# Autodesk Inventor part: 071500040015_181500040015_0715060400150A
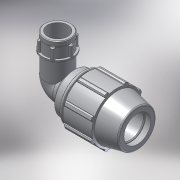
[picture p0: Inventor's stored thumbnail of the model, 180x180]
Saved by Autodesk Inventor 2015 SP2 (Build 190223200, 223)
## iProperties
Created: 2017-02
Part Number: 071500040015_181500040015_0715060400150A
Material: PVC-Piping
Description: PLASSON 90° ELBOW FEMALE ADAPTOR 40-1.1/2"
Document SubType Name: Modeling
Designer: KIM
Mass: 92.6774 g
Surface Area: 199.44 cm^2
Volume: 66.1981 cm^3
Density: 1.4 g/cm^3
Appearance: Smooth - White
Author: KIM
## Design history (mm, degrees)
derived "07150.ipt"
feature "Solid1::07150.ipt"
tag "TaggingFeature1"
body "Solid1"
other parameters: "d4" = 9.91667, "d5" = 29.75, "d7" = 82, "d9" = 17, "d11" = 3.96667, "d13" = 120 deg, "d14" = 56, "d15" = 12 deg, "d16" = 71.34, "d18" = 2, "d19" = 35 deg, "d20" = 17.5 deg, "d21" = 76.26, "d23" = 0, "d25" = 360 deg, "d27" = 1.64, "d33" = 0.8, "d42" = 44.03, "d43" = 2.46, "d46" = 1.2, "d51" = 119, "d68" = 3.96667, "d72" = 62, "d73" = 58.2985, "d74" = 25, "d75" = 67.04327, "d76" = 44.845, "d77" = 27.5, "d79" = 17.938, "d80" = 1.34535, "d83" = 0, "d84" = 0, "d91" = 61.5, "d93" = 84, "d94" = 44.845, "d95" = 31.3915, "d96" = 11.9, "d97" = 50 deg, "d98" = 40.3605, "d99" = 0.5, "d100" = 0.5, "d101" = 8.33333, "d102" = 58.2985, "d103" = 21.25, "d104" = 0, "d108" = 360 deg, "d110" = 1.74896, "E_" = 82, "A_" = 119, "l_" = 84, "l_2" = 25, "A_1" = 62, "Rp_" = 44.845, "d105" = 8.74478
